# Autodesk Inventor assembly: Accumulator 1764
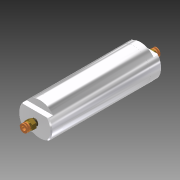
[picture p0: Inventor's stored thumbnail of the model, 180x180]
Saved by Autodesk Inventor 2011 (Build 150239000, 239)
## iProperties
Created: 2010-01
Part Number: Accumulator 1764
Document SubType Name: Assembly
Designer: cmcfadden
Author: cmcfadden
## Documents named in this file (4)
- R:\CAD Archives\Pneumatics\Accumulator 1764\Accumulator 1764.iam
- R:\CAD Archives\Pneumatics\Accumulator 1764\Air Cylinder Base 1764.ipt
- R:\CAD Archives\Pneumatics\Accumulator 1764\Air Cylinder End 1764.ipt
- R:\CAD Archives\Pneumatics\Accumulator 1764\Pneumatic Screw 1764\Pneumatic Screw 1764.iam
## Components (5 placed, 3 different names)
1. Air Cylinder Base 1764:1 — Mate:1, Tangent:1, Mate:2, Tangent:2
2. Air Cylinder End 1764:1 — Mate:1, Tangent:1, Mate:4, Mate:6
3. Air Cylinder End 1764:2 — Mate:2, Tangent:2, Mate:3, Mate:5
4. Pneumatic Screw 1764:1 [sub-assembly] — Mate:3, Mate:5
5. Pneumatic Screw 1764:2 [sub-assembly] — Mate:4, Mate:6
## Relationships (8: Mate 6, Tangent 2)
- Mate:1: Air Cylinder Base 1764:1 ↔ Air Cylinder End 1764:1
- Tangent:1: Air Cylinder Base 1764:1 ↔ Air Cylinder End 1764:1
- Mate:2: Air Cylinder Base 1764:1 ↔ Air Cylinder End 1764:2
- Tangent:2: Air Cylinder Base 1764:1 ↔ Air Cylinder End 1764:2
- Mate:3: Air Cylinder End 1764:2 ↔ Pneumatic Screw 1764:1
- Mate:4: Air Cylinder End 1764:1 ↔ Pneumatic Screw 1764:2
- Mate:5: Air Cylinder End 1764:2 ↔ Pneumatic Screw 1764:1
- Mate:6: Air Cylinder End 1764:1 ↔ Pneumatic Screw 1764:2
